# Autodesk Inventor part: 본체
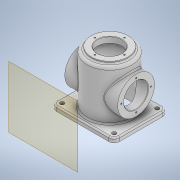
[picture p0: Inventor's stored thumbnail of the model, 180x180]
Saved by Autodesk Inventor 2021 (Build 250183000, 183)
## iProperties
Created: 2021-02
Part Number: 본체
Material: 알루미늄 6061
Document SubType Name: Modeling
Designer: 201-12
Density: 2.7 g/cm^3
Appearance: 기본값
Author: 201-12
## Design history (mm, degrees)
sketch "스케치1"
  geometry: 1 further point
sketch "스케치2"
  geometry: L1 (70, -60)-(-70, -60); L2 (-70, -60)-(-70, 60); L3 (-70, 60)-(70, 60); L4 (70, 60)-(70, -60); L5 (70, -60)-(-70, 60); L6 (-70, -60)-(70, 60); 1 further point
  constraints: 12 end point, 2 midpoint, 2 parallel, 1 horizontal, 1 perpendicular
  dimensions: "d0" = 140 distance of L2.end L3.end; "d1" = 120 distance of L1.end L2.end
extrude "돌출1" new body sketch "스케치2" distance "d2" = 10; taper "d3" = 0 deg
sketch "스케치3"
  geometry: C1 r 50 at (0, 0); 1 further point
  constraints: 1 centre point, 1 coincident
  dimensions: "d4" = 100 diameter of C1
extrude "돌출2" join sketch "스케치3" distance "d5" = 110; taper "d6" = 0 deg
sketch "스케치4"
  geometry: C1 r 41 at (0, 0); 1 further point
  constraints: 1 centre point, 1 coincident
  dimensions: "d7" = 82 diameter of C1
extrude "돌출3" join sketch "스케치4" distance "d8" = 5; taper "d9" = 0 deg
sketch "스케치5"
  geometry: C1 r 41 at (0, 60); 1 further point
  constraints: 1 centre point, 1 vertical alignment
  dimensions: "d10" = 82 diameter of C1; "d11" = 60 distance of point (0, 0) C1.centre
extrude "돌출4" join sketch "스케치5" stored distance "d12" = 118; taper "d13" = 0 deg
sketch "스케치6"
  geometry: C1 r 41 at (0, 0) reference; 2 further points
  constraints: 1 coincident
hole "구멍1" sketch "스케치6" at (0, 0) diameter "d14" = 54; stored, may be unused: countersink angle "d18" = 90 deg, drill point angle "d20" = 0 deg; dims "d15" = 7, "d16" = 4, "d17" = 2, "d19" = 9
hole "구멍2" sketch "스케치1" diameter "d21" = 84; stored, may be unused: countersink angle "d25" = 90 deg, drill point angle "d27" = 0 deg; dims "d22" = 7, "d23" = 4, "d24" = 2, "d26" = 112
sketch "스케치7"
  geometry: 2 further points
  constraints: 1 coincident
hole "구멍3" sketch "스케치7" at (0, 0) diameter "d28" = 54; stored, may be unused: countersink angle "d32" = 90 deg, drill point angle "d34" = 0 deg; dims "d29" = 7, "d30" = 4, "d31" = 2, "d33" = 112
fillet "모깎기1" dims "d35" = 12
fillet "모깎기2" dims "d36" = 3
sketch "스케치8"
  geometry: A1 r 12 centre (-58, 48) between (-58, 60) and (-70, 48) reference; A2 r 12 centre (-58, -48) between (-70, -48) and (-58, -60) reference; A3 r 12 centre (58, -48) between (58, -60) and (70, -48) reference; A4 r 12 centre (58, 48) between (70, 48) and (58, 60) reference; 5 further points
  constraints: 4 coincident
hole "구멍4" sketch "스케치8" at (-58, 48), (-58, -48), (58, -48), (58, 48) diameter "d37" = 9; stored, may be unused: countersink angle "d41" = 90 deg, drill point angle "d43" = 0 deg; dims "d38" = 7, "d39" = 4, "d40" = 2, "d42" = 112
sketch "스케치9"
  geometry: L1 (-60, -60)-(-60, -60) reference; A1 r 33 centre (0, 0) between (0, 33) and (33, 0); 4 further points
  constraints: 4 point on circle, 1 centre point, 1 point on line, 1 vertical alignment
  dimensions: "d44" = 66 diameter of A1; "d45" = 60 distance from line of L1 A1.centre
sketch "스케치10"
  geometry: 1 further point
hole "구멍5" sketch "스케치9" diameter "d46" = 3.242; stored, may be unused: countersink angle "d50" = 90 deg, drill point angle "d52" = 118 deg; dims "d47" = 8, "d48" = 4, "d49" = 2, "d51" = 10
sketch "스케치11"
  geometry: A1 r 33 centre (0, 0) between (-33, 0) and (0, -33); 3 further points
  constraints: 4 point on circle, 1 centre point, 1 coincident
  dimensions: "d53" = 66 diameter of A1
hole "구멍6" sketch "스케치11" at (0, -33), (-33, 0), (0, 33), (33, 0) diameter "d54" = 3.242; stored, may be unused: countersink angle "d58" = 90 deg, drill point angle "d60" = 118 deg; dims "d55" = 8, "d56" = 4, "d57" = 2, "d59" = 10
chamfer "모따기1" distance "d61" = 1; stored, may be unused: second distance "d62" = 2, angle "d63" = 45 deg
chamfer "모따기2" distance "d64" = 1; stored, may be unused: second distance "d65" = 2, angle "d66" = 45 deg
fillet "모깎기3" dims "d67" = 6
fillet "모깎기4" dims "d68" = 3
fillet "모깎기5" dims "d69" = 3
fillet "모깎기6" dims "d70" = 3
node "작업 평면2"
sketch "스케치13"
  geometry: 2 further points
  constraints: 1 other
feature "엠보싱1" sketch "스케치13" dims "d0" = 140, "d1" = 120, "d10" = 82, "d11" = 60, "d73" = 1, "d74" = 0
sketch "스케치14"
  geometry: L1 (-48, -60)-(48, -60) reference; C1 r 33 at (0, 0); C2 r 1.621 at (0, 33) reference; C3 r 1.621 at (-33, 0) reference; C4 r 1.621 at (0, -33) reference; C5 r 1.621 at (33, 0) reference; 6 further points
  constraints: 4 coincident, 1 centre point, 1 midpoint, 1 vertical alignment
  dimensions: "d75" = 66 diameter of C1; "d76" = 60 distance from line of L1 C1.centre
hole "구멍7" sketch "스케치14" at (0, 33), (-33, 0), (0, -33), (33, 0) diameter "d77" = 3.242; stored, may be unused: countersink angle "d81" = 90 deg, drill point angle "d83" = 118 deg; dims "d78" = 8, "d79" = 4, "d80" = 2, "d82" = 10
node "솔리드1"
mirror "미러1"
node "투영된 루프1"
feature "A9D066F2-1C7D-4E18-AEED-F7BC21143FA4" dims "d14" = 54, "d15" = 7, "d16" = 4, "d17" = 2, "d18" = 90 deg, "d19" = 9, "d20" = 0
other parameters: "d72" = 147.6375
